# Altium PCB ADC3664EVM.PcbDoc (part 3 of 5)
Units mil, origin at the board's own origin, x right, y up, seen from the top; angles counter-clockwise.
Board outline 3900 x 2716.54 mil, 10 copper layers (Top Layer, L2 GND, L3 PWR, L4 GND, L5 SIG, L6 GND, L7 GND, L8 PWR, L9 GND, Bottom Layer), stack 61.2 mil thick; 332 components, 223 nets, 1425 pads, 969 vias.
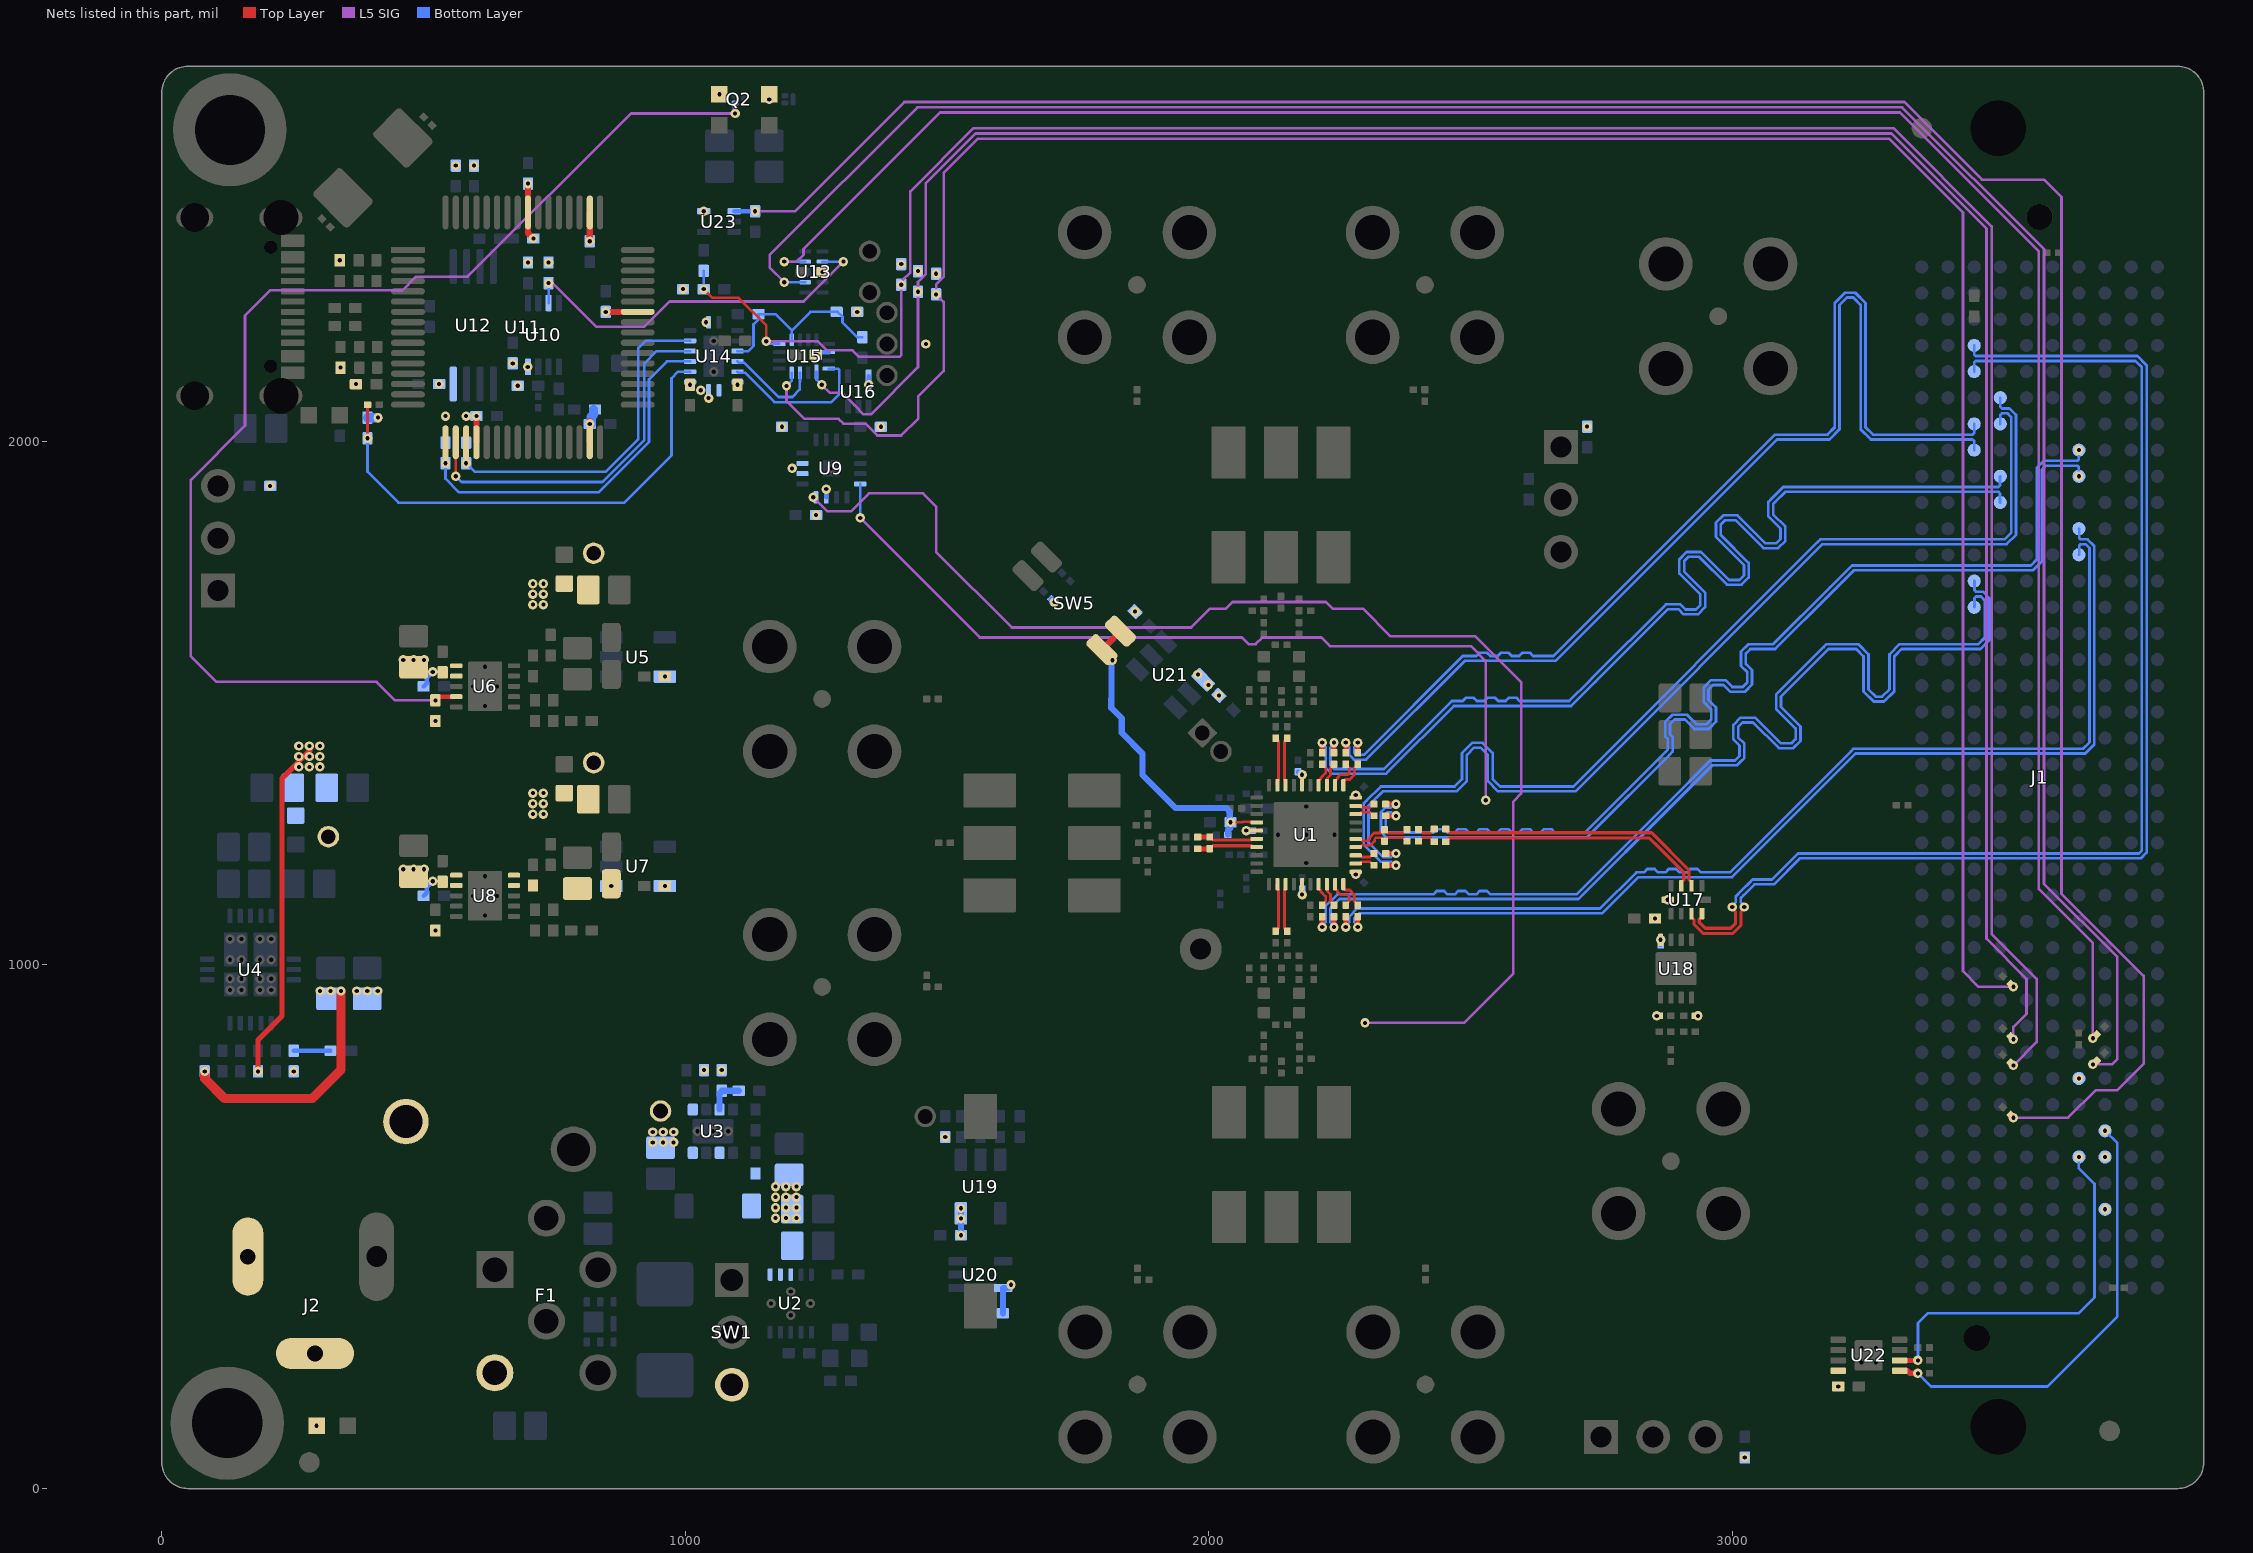
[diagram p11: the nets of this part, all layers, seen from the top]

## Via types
v1: diameter 18, hole 8, Top Layer to Bottom Layer, tented both sides, 952 vias
v2: diameter 40, hole 20, Top Layer to Bottom Layer, tented both sides, 14 vias
v3: diameter 18, hole 8, Top Layer to Bottom Layer, tented bottom, 3 vias

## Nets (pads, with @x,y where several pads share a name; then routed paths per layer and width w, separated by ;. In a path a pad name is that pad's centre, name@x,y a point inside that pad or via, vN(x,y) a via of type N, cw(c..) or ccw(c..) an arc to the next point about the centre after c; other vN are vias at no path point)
1p8V_AVDD: C21.2 C74.2 C75.2 C76.2 FB2.2 PP3.1 U1.5 U1.15 U1.36 U9.8 | length 2600.6
  Top Layer w8: v1(2071.2,1256.67) U1.5@2091.2,1256.67 ; v1(2177.82,1134.31) U1.15@2177.82,1154.31 ; U1.36@2177.82,1343.29 v1(2177.82,1363.29)
  L5 SIG w5: v1(1244.37,1893.18) 1270.87,1866.68 1316.83,1866.68 1350.74,1900.58 1453.75,1900.58 1479.06,1875.27 1479.06,1789.12 1623.6,1644.58 1965.79,1644.58 2001.71,1680.5 2032.12,1680.5 2044.95,1693.33 2223.48,1693.33 2236.31,1680.5 2294.03,1680.5 2346.78,1627.75 2508.63,1627.75 2596.37,1540 2596.37,1327.15 2581.25,1312.02 2581.25,983.33 2487.32,889.4 v1(2298.05,889.4)
  Bottom Layer w5: v1(1244.37,1893.18) U9.8@1249.37,1893.18
  Bottom Layer w8: v1(2071.2,1256.67) C75.2@2082.49,1256.67 ; C76.2@2170,1368.98 2170,1368.19 2175.93,1362.26 2176.79,1362.26 v1(2177.82,1363.29) ; v1(2177.82,1134.31) C74.2@2177.82,1144.88
  other v1: 708.74,1688.25 728.74,1688.25 708.74,1708.25 728.74,1708.25 708.74,1728.25 728.74,1728.25
1p8V_IOVDD: C27.2 C77.2 C78.2 FB3.2 PP4.1 U1.21 U1.30 U9.4 | length 1659.5
  Top Layer w8: v1(2280.18,1172.93) U1.21@2280.18,1177.93 ; U1.30@2280.18,1319.66 v1(2280.18,1324.66)
  L5 SIG w5: v1(1334.01,1853.77) 1562.37,1625.41 2062.89,1625.41 2075.65,1612.66 2089.32,1612.66 2102.08,1625.41 2214.74,1625.41 2231.24,1608.91 2500.47,1608.91 2528.47,1580.91 v1(2528.47,1314.42)
  Bottom Layer w5: v1(1334.01,1853.77) U9.4@1334.01,1918.77
  other v1: 708.74,1288.25 728.74,1288.25 708.74,1308.25 728.74,1308.25 708.74,1328.25 728.74,1328.25
1p8V_LVLSHIFT: C26.2 C46.2 C82.2 R27.1 R28.2 R56.1 R59.2 R60.2 R61.2 R111.2 R122.2 R124.1 R130.2 R148.1 U7.1 U8.9 U8.10 U14.15 U16.5 U19.5 U20.5 U23.5 | length 148.5
  Bottom Layer w5: v1(1099.53,2108.3) U14.15@1099.53,2113.3
  Bottom Layer w9: v1(1350,2108.49) U16.5@1350,2124.23
  Bottom Layer w12: C82.2@1526.23,483.68 v1(1526.21,535.51) ; R124.1@1606.46,334.78 1606.69,335.01 1606.69,382.82 U20.5@1606.92,383.05 1615.82,383.05 ccw(c1615.82,389.15) 1616.84,383.13 U20.5@1621.84,388.13 ; R130.2@1699.72,1697.94 1704.1,1693.55 1705.33,1693.55 v1(1704.72,1692.94) ; U20.5@1621.84,388.13 ccw(c1615.82,389.15) v1(1621.93,389.15) 1621.93,388.22 U20.5@1621.84,388.13
  other v1: 1526.26,483.65 1526.21,515.51 1496.21,671.34 858.46,1150.75 2722.25,2028.25 1459.37,2185.97 1328.11,2247.34 995.55,2290.74 1478.89,2320.15 1444.21,2325.15 1412.13,2338.64 1034.92,2439.49
2p3V: C14.2 C15.2 C18.2 C19.2 C24.2 C25.2 FB1.2 PP2.1 R12.2 R16.2 R26.2 U6.1 U6.2 U8.1 U8.2 | length 854.7
  Top Layer w8: v1(460.98,1182.66) 474.98,1168.66 C24.2@480.98,1168.66 ; v1(460.98,1582.66) 474.98,1568.66 C18.2@480.98,1568.66 ; v1(480.98,1182.66) C24.2@480.98,1168.66 ; v1(480.98,1582.66) C18.2@480.98,1568.66 ; v1(500.98,1182.66) 486.98,1168.66 C24.2@480.98,1168.66 ; v1(500.98,1582.66) 486.98,1568.66 C18.2@480.98,1568.66
  Top Layer w10: v1(183.89,796.75) 183.89,856.68 229.77,902.57 229.77,1356.43 282.4,1409.06
  Bottom Layer w8: R26.2@499.93,1132.05 500.25,1132.05 506.09,1137.89 506.09,1148.51 v1(517.4,1159.81) ; R16.2@499.93,1532.05 500.25,1532.05 506.09,1537.89 506.09,1548.51 v1(517.4,1559.81)
  other v1: 261.89,1378.18 281.89,1378.18 301.89,1378.18 261.89,1398.18 281.89,1398.18 301.89,1398.18 261.89,1418.18 281.89,1418.18 301.89,1418.18
3p3V_AUX: J1.D32
  other v1: 3661.42,783.27
3p3V_EEPROM: C89.2 U22.8
  other v1: 3201.8,194.99
3p3V_Utility: C7.2 C17.2 C23.2 C29.2 C30.2 C36.2 C37.2 C38.2 C39.2 C40.2 C41.2 C44.2 C45.2 C47.2 C55.2 C56.2 C86.2 FB4.1 FB5.1 PP1.1 R5.2 R7.2 R10.2 R15.2 R24.2 R32.2 R33.2 R34.2 R35.1 R37.2 R38.1 R41.2 R47.2 R48.2 R49.2 R51.2 R52.2 R53.2 R54.2 R69.2 R70.2 R75.2 R131.2 U3.4 U3.5 U5.5 U7.5 U9.7 U9.10 U9.11 U10.8 U11.20 U11.31 U11.42 U11.50 U11.56 U12.8 U13.8@1261.85,2323.6 U14.1 U14.2 U14.8 U14.16 U15.14 U17.10 U18.8 U21.4 | length 429.1
  Top Layer w11: v1(847.98,2247.34) U11.42@908.98,2247.34
  Top Layer w12: U11.20@600.91,1998.32 v1(600.91,2048.32) ; v1(699.33,2492.3) U11.56@699.33,2437.3 699.33,2397.82 v1(709.66,2387.5) ; U11.31@817.44,1998.32 v1@817.44,2038.32 ; v1(817.44,2382.3) U11.50@817.44,2437.3
  Bottom Layer w5: v1(1008.98,2108.3) U14.2@1008.98,2113.3 ; v1(1039.41,2227.47) U14.8@1044.41,2227.47
  Bottom Layer w8: v1(1249.02,2165.39) 1251.72,2165.39 1256.72,2170.39 U15.14@1274.02,2170.39 ; C56.2@2862.58,1038.42 v1(2862.58,1047.98)
  Bottom Layer w9: U9.7@1269.05,1893.18 v1(1269.05,1908.92)
  Bottom Layer w18: R52.2@392.95,2045.32 v1(412.95,2045.32) ; v1(817.44,2033.32) 819.41,2033.32 820.25,2034.16 820.25,2047 824.48,2051.23 R38.1@824.48,2060.88
  other v1: 3023.45,59.35 937.5,660.99 957.5,660.99 977.5,660.99 937.5,680.99 957.5,680.99 977.5,680.99 251.89,796.75 1035.7,799.2 1069.29,799.2 2855.22,902.74 2934,902.74 522.48,1065.91 2851.78,1088.72 2876.36,1124.55 960.83,1150.75 522.48,1465.91 2018.88,1514.78 1998.88,1534.78 960.83,1550.75 1978.88,1554.78 1858.78,1674.87 1249.63,1859.23 206.85,1915 1203.78,1948.29 1184.41,2027.82 1373.38,2027.82 541.85,2048.32 581.22,2048.32 1044.41,2082.55 1029.41,2097.55 679.65,2106.22 370.63,2109.54 529.61,2109.54 341.37,2140.87 699.03,2142.22 670.29,2148.91 1261.85,2323.6 699.33,2341.64 738.7,2341.64 340,2345.76 561.54,2526.67 596.22,2526.67
3p3VU_PG: R5.1 R9.2 U3.7 | length 70.4
  Bottom Layer w12: U3.7@1065.29,723.83 1065.29,753.86 1069.29,757.86 R5.1@1069.29,759.83 R9.2@1102.03,759.83
12V: C2.2 C3.2 C6.2 C9.2 C10.2 D1.1 D3.1 D4.1 D5.1 R6.2 R11.2 U2.6 U2.7 U2.8 U3.2 U4.18 | length 462.9
  Top Layer w18: v1(81.89,796.75) 81.89,783.11 120,745 287.48,745 342.26,799.78 v1(342.26,950.2)
  other v1: 295.33,119.85 1172.07,516.64 1192.07,516.64 1212.07,516.64 1172.07,536.64 1192.07,536.64 1212.07,536.64 1172.07,556.64 1192.07,556.64 1212.07,556.64 1172.07,576.64 1192.07,576.64 1212.07,576.64 302.26,950.2 322.26,950.2 372.26,950.2 392.26,950.2 412.26,950.2 1160,2653.11 1065,2663.11
12V_FMC: J1.C35 J1.C37 SW1.3
  other v1: 3711.42,533.27 3711.42,633.27
AIN_N: R87.2 U1.13 | length 93.3
  Top Layer w6.1: U1.13@2146.32,1154.31 2146.32,1146.44 2144,1144.11 2144,1070.85 2149.75,1065.1 R87.2@2149.75,1064.31
AIN_P: R79.2 U1.12 | length 93.3
  Top Layer w6.1: R79.2@2127.15,1064.31 2127.15,1065.1 2132.9,1070.85 2132.9,1144.11 2130.57,1146.44 U1.12@2130.57,1154.31
AVDD_PG: Q2.1@1095,2646.22 R15.1 U6.4 | length 2355.2
  Top Layer w8: v1(522.48,1505.28) 522.48,1506.52 528.32,1512.36 U6.4@562.48,1512.36
  L5 SIG w5: v1(522.48,1505.28) 445.42,1505.28 410,1540.7 104.24,1540.7 55.51,1589.43 55.51,1926.56 158.81,2029.87 158.81,2240.25 206.85,2288.29 459.46,2288.29 485.67,2314.49 584.28,2314.49 896.01,2626.22 v1(1095,2626.22)
  Bottom Layer w9.7: v1(1095,2626.22) Q2.1@1095,2646.22
BIN_N: R91.2 U1.38 | length 93.3
  Top Layer w6.1: U1.38@2146.32,1343.29 2146.32,1351.16 2144,1353.48 2144,1400.97 2144,1426.75 2149.75,1432.5 R91.2@2149.75,1433.29
BIN_P: R99.2 U1.39 | length 93.3
  Top Layer w6.1: R99.2@2127.15,1433.29 2127.15,1432.5 2132.9,1426.75 2132.9,1405.57 2132.9,1353.48 2130.57,1351.16 U1.39@2130.57,1343.29
CLK_N: C54.2 R65.1 U1.7 | length 115.8
  Top Layer w6.1: R65.1@2001.99,1221.75 2007.74,1227.5 2081,1227.5 2083.33,1225.18 U1.7@2091.2,1225.18
  Top Layer w9.7: C54.2@1978.2,1221.75 1994.35,1221.75 1994.9,1222.3 R65.1@2001.2,1222.3
CLK_P: C48.2 R65.2 U1.6 | length 116.3
  Top Layer w6.1: R65.2@2001.2,1244.35 2001.99,1244.35 2007.74,1238.6 2081,1238.6 2083.33,1240.92 U1.6@2091.2,1240.92
  Top Layer w9.7: C48.2@1978.2,1244.35 R65.2@2001.2,1244.35
CTRL: C87.2 C88.2 SW5.3 SW5.4 U1.4 | length 615.6
  Top Layer w5: v1(2041.2,1272.42) 2063.62,1272.42 2064.37,1273.17 2078.04,1273.17 2078.79,1272.42 U1.4@2091.2,1272.42
  Top Layer w12: v1(1815.55,1582.1) SW5.4@1795.55,1602.1 1806.13,1612.68 SW5.3@1830.91,1637.45
  Bottom Layer w12: v1(1815.55,1582.1) 1814.41,1580.95 1814.41,1576.71 1813.79,1576.09 1813.79,1507.94 1813.35,1507.51 1813.35,1490.94 1833.45,1470.85 1833.45,1443.35 1872.93,1403.87 1872.93,1363.32 1936.59,1299.66 2022.44,1299.66 2022.68,1299.91 2032.67,1299.91 2039.7,1292.88 2039.7,1273.92 v1(2041.2,1272.42) 2041.2,1262.58 2036.2,1257.58 C88.2@2036.2,1249.42
DA0_DUT_N: R113.1 U1.19 | length 62
  Top Layer w5.2: U1.19@2240.81,1154.31 2240.81,1146.44 2245.02,1142.22 2245.02,1140.5 2251.47,1134.05 2265.01,1134.05 2268.06,1131.01 2268.06,1121.8 2261.36,1115.1 R113.1@2261.36,1114.31
DA0_DUT_P: R112.1 U1.20 | length 56.7
  Top Layer w5.2: U1.20@2256.56,1154.31 2256.56,1146.44 2259.74,1143.25 2268.82,1143.25 2277.26,1134.82 2277.26,1121.8 2283.96,1115.1 R112.1@2283.96,1114.31
DA0_N: J1.D12 R113.2 | length 2023.1
  Top Layer w9.7: v1(2261.36,1072.26) R113.2@2261.36,1092.26
  Bottom Layer w5.2: v1(2261.36,1072.26) 2261.36,1075.01 2268.06,1081.71 2268.06,1092.87 2283,1107.81 2747.01,1107.81 2816.13,1176.93 2830.77,1176.93 2837.11,1183.27 2851.25,1183.27 2857.58,1176.93 2871.72,1176.93 2878.05,1183.27 2892.19,1183.27 2898.53,1176.93 2912.66,1176.93 2919,1183.27 2933.14,1183.27 2939.47,1176.93 2995.19,1176.93 3225.93,1407.68 3231.32,1413.07 3669.78,1413.07 3681.62,1424.9 3681.62,1796.19 3674.14,1803.67 3665,1803.67 3661.95,1800.62 3661.95,1783.8 J1.D12@3661.42,1783.27
DA0_P: J1.D11 R112.2 | length 2022.6
  Top Layer w9.7: v1(2283.96,1072.26) R112.2@2283.96,1092.26
  Bottom Layer w5.2: v1(2283.96,1072.26) 2283.96,1075.01 2277.26,1081.71 2277.26,1089.06 2286.81,1098.61 2750.82,1098.61 2819.94,1167.73 2999,1167.73 3235.13,1403.87 3673.6,1403.87 3690.82,1421.09 3690.82,1800 3677.95,1812.87 3665,1812.87 3661.95,1815.91 3661.95,1832.73 J1.D11@3661.42,1833.27
DA1_DUT_N: R115.1 U1.17 | length 48.4
  Top Layer w5.2: U1.17@2209.31,1154.31 2209.31,1146.44 2213.52,1142.22 2213.52,1140.34 2222.86,1131.01 2222.86,1121.8 2216.16,1115.1 R115.1@2216.16,1114.31
DA1_DUT_P: R114.1 U1.18 | length 45.7
  Top Layer w5.2: U1.18@2225.06,1154.31 2226.24,1153.13 2226.24,1140.64 2232.06,1134.82 2232.06,1121.8 2238.76,1115.1 R114.1@2238.76,1114.31
DA1_N: J1.H14 R115.2 | length 2018.6
  Top Layer w9.7: v1(2216.16,1072.26) R115.2@2216.16,1092.26
  Bottom Layer w5.2: v1(2216.16,1072.26) 2216.16,1075.01 2222.86,1081.71 2222.86,1112.52 2245.32,1134.97 2428.65,1134.97 2434.98,1141.31 2449.12,1141.31 2455.45,1134.97 2469.59,1134.97 2475.93,1141.31 2490.06,1141.31 2496.4,1134.97 2510.54,1134.97 2516.87,1141.31 2531.01,1141.31 2537.34,1134.97 2701.71,1134.97 2876.4,1309.67 2957.41,1390.68 2984.93,1390.68 3004.83,1390.68 3013.36,1399.21 3013.36,1419.1 3001.5,1430.96 3001.5,1458.48 3015.42,1472.4 3042.94,1472.4 3092.15,1423.19 3112.04,1423.19 3120.57,1431.72 3120.57,1451.61 3083.22,1488.97 3083.22,1516.49 3089.66,1522.93 3174.01,1607.28 3179.4,1612.67 3200,1612.67 3239.98,1612.67 3259.44,1593.21 3259.44,1526.48 3273.51,1512.41 3285.57,1512.41 3299.64,1526.48 3299.64,1593.21 3319.09,1612.67 3328.2,1612.67 3469.38,1612.67 3481.62,1624.9 3481.62,1696.19 3474.14,1703.67 3465,1703.67 3461.95,1700.62 3461.95,1683.8 J1.H14@3461.42,1683.27
DA1_P: J1.H13 R114.2 | length 2018.1
  Top Layer w9.7: v1(2238.76,1072.26) R114.2@2238.76,1092.26
  Bottom Layer w5.2: v1(2238.76,1072.26) 2238.76,1075.01 2232.06,1081.71 2232.06,1108.71 2249.13,1125.77 2705.52,1125.77 2882.91,1303.17 2961.22,1381.48 2981.12,1381.48 3008.64,1381.48 3016.59,1389.43 3022.56,1395.4 3022.56,1422.91 3010.7,1434.77 3010.7,1454.67 3019.23,1463.2 3039.13,1463.2 3088.34,1413.99 3115.85,1413.99 3129.77,1427.91 3129.77,1455.43 3092.42,1492.78 3092.42,1512.68 3096.16,1516.42 3183.21,1603.47 3200,1603.47 3236.17,1603.47 3250.24,1589.4 3250.24,1522.67 3269.69,1503.21 3289.38,1503.21 3308.84,1522.67 3308.84,1589.4 3322.91,1603.47 3328.2,1603.47 3473.19,1603.47 3490.82,1621.09 3490.82,1700 3477.95,1712.87 3465,1712.87 3461.95,1715.91 3461.95,1732.73 J1.H13@3461.42,1733.27
DB0_DUT_N: R117.1 U1.32 | length 62
  Top Layer w5.2: U1.32@2240.81,1343.29 2240.81,1351.16 2245.02,1355.37 2245.02,1357.09 2251.47,1363.54 2265.01,1363.54 2268.06,1366.59 2268.06,1375.8 2261.36,1382.5 R117.1@2261.36,1383.29
DB0_DUT_P: R116.1 U1.31 | length 56.7
  Top Layer w5.2: U1.31@2256.56,1343.29 2256.56,1351.16 2259.74,1354.34 2268.82,1354.34 2277.26,1362.78 2277.26,1375.8 2283.96,1382.5 R116.1@2283.96,1383.29
DB0_N: J1.H8 R117.2 | length 2018.1
  Top Layer w9.7: R117.2@2261.36,1404.62 R117.2@2261.36,1405.33 v1(2261.36,1424.62)
  Bottom Layer w5.2: v1(2261.36,1424.62) 2261.36,1421.88 2268.06,1415.18 2268.06,1401.18 2277.17,1392.06 2299.76,1392.06 2488.5,1580.8 2661.92,1580.8 3084.79,2003.67 3175.86,2003.67 3184.97,2003.67 3204.43,2023.13 3204.43,2260.64 3218.5,2274.71 3230.56,2274.71 3244.63,2260.64 3244.63,2023.13 3264.09,2003.67 3299.64,2003.67 3458.37,2003.67 3461.42,2000.62 J1.H8@3461.42,1983.27
DB0_P: J1.H7 R116.2 | length 2018.6
  Top Layer w9.7: R116.2@2283.96,1404.62 R116.2@2283.96,1405.33 v1(2283.96,1424.62)
  Bottom Layer w5.2: v1(2283.96,1424.62) 2283.96,1421.88 2277.26,1415.18 2277.26,1404.99 2280.98,1401.26 2295.95,1401.26 2484.69,1590 2510.54,1590 2516.87,1596.34 2531.01,1596.34 2537.34,1590 2551.48,1590 2557.82,1596.34 2571.95,1596.34 2578.29,1590 2592.43,1590 2598.76,1596.34 2612.9,1596.34 2619.23,1590 2658.11,1590 3080.98,2012.87 3175.86,2012.87 3181.16,2012.87 3195.23,2026.94 3195.23,2264.45 3214.69,2283.91 3234.37,2283.91 3253.83,2264.45 3253.83,2026.94 3267.9,2012.87 3299.64,2012.87 3458.37,2012.87 3461.42,2015.91 J1.H7@3461.42,2033.27
DB1_DUT_N: R119.1 U1.34 | length 48.4
  Top Layer w5.2: U1.34@2209.31,1343.29 2209.31,1351.16 2213.52,1355.37 2213.52,1357.25 2222.86,1366.59 2222.86,1375.8 2216.16,1382.5 R119.1@2216.16,1383.29
DB1_DUT_P: R118.1 U1.33 | length 45.7
  Top Layer w5.2: U1.33@2225.06,1343.29 2226.24,1344.47 2226.24,1356.96 2232.06,1362.78 2232.06,1375.8 2238.76,1382.5 R118.1@2238.76,1383.29
DB1_N: J1.G10 R119.2 | length 2018.3
  Top Layer w9.7: R119.2@2216.16,1404.62 R119.2@2216.16,1405.33 v1(2216.16,1424.62)
  Bottom Layer w5.2: v1(2216.16,1424.62) 2216.16,1421.88 2222.86,1415.18 2222.86,1377.52 2235.43,1364.95 2337.84,1364.95 2343.23,1370.34 2467.66,1494.78 2691.71,1494.78 2730.3,1533.37 2738.09,1541.16 2876.48,1679.55 2896.38,1679.55 2906.27,1669.65 2933.79,1669.65 2947.71,1683.57 2947.71,1711.09 2907.6,1751.19 2907.6,1771.09 2916.13,1779.62 2936.03,1779.62 2989.4,1726.25 3016.92,1726.25 3030.84,1740.16 3030.84,1767.68 2977.47,1821.05 2977.47,1840.95 2985.99,1849.48 3005.89,1849.48 3059.26,1796.11 3086.78,1796.11 3100.7,1810.03 3100.7,1837.54 3077.54,1860.71 3077.54,1880.61 3081.28,1884.35 3100.6,1903.67 3507.84,1903.67 3510.88,1900.62 3510.88,1883.8 J1.G10@3511.42,1883.27
DB1_P: J1.G9 R118.2 | length 2018.8
  Top Layer w9.7: R118.2@2238.76,1404.62 R118.2@2238.76,1405.33 v1(2238.76,1424.62)
  Bottom Layer w5.2: v1(2238.76,1424.62) 2238.76,1421.88 2232.06,1415.18 2232.06,1381.33 2239.24,1374.15 2334.03,1374.15 2463.85,1503.98 2484.69,1503.98 2491.02,1510.31 2505.16,1510.31 2511.49,1503.98 2525.63,1503.98 2531.97,1510.31 2546.1,1510.31 2552.44,1503.98 2566.58,1503.98 2572.91,1510.31 2587.05,1510.31 2593.38,1503.98 2687.89,1503.98 2726.49,1542.57 2731.58,1547.66 2872.67,1688.75 2900.19,1688.75 2910.08,1678.85 2929.98,1678.85 2938.51,1687.38 2938.51,1707.28 2898.4,1747.38 2898.4,1774.9 2912.32,1788.82 2939.84,1788.82 2993.21,1735.45 3013.11,1735.45 3021.64,1743.97 3021.64,1763.87 2968.27,1817.24 2968.27,1844.76 2982.18,1858.68 3009.7,1858.68 3063.07,1805.31 3082.97,1805.31 3091.5,1813.84 3091.5,1833.73 3068.34,1856.9 3068.34,1884.42 3074.77,1890.86 3096.79,1912.87 3507.84,1912.87 3510.88,1915.91 3510.88,1932.73 J1.G9@3511.42,1933.27
DC-DC_PG: R10.1 R23.2 U4.19 | length 70.2
  Bottom Layer w8: R10.1@251.89,836.12 R23.2@322.11,836.12
DCLK_DUT_N: R108.1 U1.22 | length 39.1
  Top Layer w5.2: U1.22@2280.18,1193.68 2288.05,1193.68 2291.33,1196.95 2307.69,1196.95 2314.39,1190.25 R108.1@2315.18,1190.25
DCLK_DUT_P: R107.1 U1.23 | length 39.1
  Top Layer w5.2: U1.23@2280.18,1209.43 2288.05,1209.43 2291.33,1206.15 2307.69,1206.15 2314.39,1212.85 R107.1@2315.18,1212.85
DCLK_N: J1.G7 R108.2 | length 2017.9
  Top Layer w9.7: R108.2@2337.23,1190.25 v1(2357.23,1190.25)
  Bottom Layer w5.2: v1(2357.23,1190.25) 2354.48,1190.25 2347.78,1196.95 2328.56,1196.95 2323.17,1202.34 2301.05,1224.46 2295.66,1229.85 2295.66,1308.4 2301.05,1313.79 2328.14,1340.87 2463.85,1340.87 2469.15,1340.87 2483.22,1354.94 2483.22,1404.71 2502.67,1424.17 2522.36,1424.17 2541.82,1404.71 2541.82,1354.94 2555.89,1340.87 2645,1340.87 2695.87,1340.87 3162.48,1807.48 3167.87,1812.87 3519.58,1812.87 3532.02,1825.3 3532.02,2046.87 3525.22,2053.67 3514.46,2053.67 3511.42,2050.62 J1.G7@3511.42,2033.27
DCLK_P: J1.G6 R107.2 | length 2017.9
  Top Layer w9.7: R107.2@2337.23,1212.85 v1(2357.23,1212.85)
  Bottom Layer w5.2: v1(2357.23,1212.85) 2354.48,1212.85 2347.78,1206.15 2332.37,1206.15 2304.86,1233.66 2304.86,1304.59 2331.95,1331.67 2463.85,1331.67 2472.96,1331.67 2492.42,1351.13 2492.42,1400.9 2506.49,1414.97 2518.55,1414.97 2532.62,1400.9 2532.62,1351.13 2552.07,1331.67 2645,1331.67 2699.68,1331.67 3171.68,1803.67 3523.39,1803.67 3541.22,1821.49 3541.22,2050.68 3529.03,2062.87 3514.46,2062.87 3511.42,2065.91 J1.G6@3511.42,2083.27
DCLKIN_DUT_N: R103.2 R105.1 U1.24 | length 115.7
  Top Layer w5: U1.24@2280.18,1225.18 2288.05,1225.18 2291.43,1228.55 2308.18,1228.55 2316.38,1236.75 2316.38,1240.05 2319.31,1242.97 2329.44,1242.97 R103.2@2335.18,1237.24 ; R103.2@2335.18,1236.45 R103.2@2335.18,1237.24 ; R105.1@2378.18,1236.15 2377.39,1236.15 2373.59,1239.95 2373.59,1240.05 2370.66,1242.97 2340.92,1242.97 R103.2@2335.18,1237.24
DCLKIN_DUT_P: R103.1 R104.1 U1.25 | length 115.7
  Top Layer w5: U1.25@2280.18,1240.92 2288.05,1240.92 2291.43,1237.55 2304.45,1237.55 2307.38,1240.48 2307.38,1243.77 2315.58,1251.97 2329.44,1251.97 R103.1@2335.18,1257.71 ; R103.1@2335.18,1258.5 R103.1@2335.18,1257.71 ; R104.1@2378.18,1258.8 2377.39,1258.8 2373.59,1255 2373.59,1254.9 2370.66,1251.97 2340.92,1251.97 R103.1@2335.18,1257.71
DCLKIN_N: R72.2 R104.2 | length 36.6
  Top Layer w5: R104.2@2400.23,1258.8 2401.01,1258.8 2404.81,1255 2404.81,1254.9 2407.74,1251.97 2422.71,1251.97 2425.64,1254.9 2425.64,1255.8 2429.44,1259.6 R72.2@2430.23,1259.6
DCLKIN_P: R71.2 R105.2 | length 36.6
  Top Layer w5: R105.2@2400.23,1236.15 2401.01,1236.15 2404.81,1239.95 2404.81,1240.05 2407.74,1242.97 2422.71,1242.97 2425.64,1240.05 2425.64,1239.15 2429.44,1235.35 R71.2@2430.23,1235.35
DCLKIN_SMA_N: R72.1 U17.7 | length 529.4
  Top Layer w6.1: R72.1@2452.27,1259.6 2453.06,1259.6 2456.31,1256.35 2456.31,1256.1 2459.88,1252.53 2845.43,1252.53 2916.84,1181.11 2916.84,1162.48 2920.42,1158.9 2920.75,1158.9 2921.64,1158.02 U17.7@2921.64,1151.13
DCLKIN_SMA_P: R71.1 U17.8 | length 512.7
  Top Layer w6.1: R71.1@2452.27,1235.35 2453.06,1235.35 2456.31,1238.6 2456.31,1238.85 2459.88,1242.43 2841.25,1242.43 2858.92,1224.75 2906.74,1176.93 2906.74,1162.48 2903.17,1158.9 2902.84,1158.9 2901.95,1158.02 U17.8@2901.95,1151.13
EXTGND: F1.3 J2.2 J2.3 TP2.1
FCLK_DUT_N: R110.1 U1.29 | length 39.1
  Top Layer w5.2: U1.29@2280.18,1303.92 2288.05,1303.92 2291.33,1300.64 2307.69,1300.64 2314.39,1307.34 R110.1@2315.18,1307.34
FCLK_DUT_P: R109.1 U1.28 | length 39.1
  Top Layer w5.2: U1.28@2280.18,1288.17 2288.05,1288.17 2291.33,1291.44 2307.69,1291.44 2314.39,1284.74 R109.1@2315.18,1284.74
FCLK_N: J1.D9 R110.2 | length 2017.4
  Top Layer w9.7: R110.2@2337.23,1307.34 v1(2357.23,1307.34)
  Bottom Layer w5.2: v1(2357.23,1307.34) 2354.48,1307.34 2347.78,1300.64 2336.97,1300.64 2328.53,1292.21 2328.53,1253.77 2338.45,1243.85 2721.86,1243.85 2727.25,1249.24 2879.18,1401.17 2885.62,1407.61 2885.62,1435.13 2880.44,1440.32 2880.44,1460.21 2888.97,1468.74 2908.87,1468.74 2926.93,1450.68 2954.45,1450.68 2968.36,1464.6 2968.36,1492.12 2954.17,1506.31 2954.17,1526.21 2962.69,1534.74 2982.59,1534.74 2995.77,1521.57 3023.29,1521.57 3037.2,1535.48 3037.2,1563 3025.35,1574.86 3025.35,1594.75 3033.87,1603.28 3053.77,1603.28 3081.29,1603.28 3192.28,1714.27 3231.88,1753.87 3349.24,1753.87 3573.6,1753.87 3590.82,1771.09 3590.82,1946.4 3598.08,1953.67 3658.37,1953.67 3661.42,1950.62 v1(3661.42,1933.27)
FCLK_P: J1.D8 R109.2 | length 2018.4
  Top Layer w9.7: R109.2@2337.23,1284.74 v1(2357.23,1284.74)
  Bottom Layer w5.2: v1(2357.23,1284.74) 2354.48,1284.74 2347.78,1291.44 2340.78,1291.44 2337.73,1288.4 2337.73,1257.58 2342.26,1253.05 2428.65,1253.05 2434.98,1259.39 2449.12,1259.39 2455.45,1253.05 2469.59,1253.05 2475.93,1259.39 2490.06,1259.39 2496.4,1253.05 2510.54,1253.05 2516.87,1259.39 2531.01,1259.39 2537.34,1253.05 2551.48,1253.05 2557.82,1259.39 2571.95,1259.39 2578.29,1253.05 2592.43,1253.05 2598.76,1259.39 2612.9,1259.39 2619.23,1253.05 2633.37,1253.05 2639.71,1259.39 2653.84,1259.39 2660.18,1253.05 2718.05,1253.05 2872.68,1407.68 2876.42,1411.42 2876.42,1431.32 2871.24,1436.51 2871.24,1464.02 2885.16,1477.94 2912.68,1477.94 2930.74,1459.88 2950.64,1459.88 2959.16,1468.41 2959.16,1488.31 2944.97,1502.5 2944.97,1530.02 2958.88,1543.94 2986.4,1543.94 2999.58,1530.76 3019.47,1530.76 3028,1539.29 3028,1559.19 3016.15,1571.05 3016.15,1598.57 3030.06,1612.48 3057.58,1612.48 3077.48,1612.48 3185.77,1720.77 3228.07,1763.07 3353.05,1763.07 3569.78,1763.07 3581.62,1774.9 3581.62,1950.21 3594.27,1962.87 3658.37,1962.87 3661.42,1965.91 v1(3661.42,1983.27)
FMC_C\S\_DUT_LVLS: R60.1 R143.1 U15.4 | length 4447.5
  Top Layer w5: R143.1@3531.71,962.97 v3(3536.42,958.27)
  L5 SIG w5: v1(1193.15,2106.02) 1193.15,2077.4 1227.45,2043.1 1292.36,2043.1 1301.74,2033.72 1344.15,2033.72 1366.55,2011.32 1412.13,2011.32 1444.85,2044.05 1444.85,2086.22 1493.1,2134.47 1493.1,2266.58 v1(1478.89,2280.78) 1478.89,2299.65 1493.39,2314.15 1493.39,2512.94 1558.54,2578.09 3298.99,2578.09 3440,2437.08 3440,988.27 3470,958.27 v3(3536.42,958.27)
  Bottom Layer w5: v1(1193.15,2106.02) 1203.15,2116.02 U15.4@1203.15,2131.02
FMC_I2C_SCL: R140.1 U13.4 | length 4395.1
  Top Layer w10: v1(3688.23,860.08) R140.1@3694.85,866.7
  L5 SIG w5: v1(1188.98,2343.28) 1212.63,2343.28 1225.48,2356.13 1225.48,2367.09 1486.47,2628.09 2620,2628.09 ; 2790,2628.09 2620,2628.09 ; v1(3688.23,860.08) 3688.23,1041.77 3584.92,1145.08 3584.92,2362.87 3319.7,2628.09 2620,2628.09
  Bottom Layer w5: v1(1188.98,2343.28) U13.4@1228.98,2343.28
FMC_I2C_SDA: R141.1 U13.2 | length 4601.8
  Top Layer w10: v1(3688.23,810.08) R141.1@3694.85,816.7
  L5 SIG w5: v1(1188.98,2303.91) 1161.11,2331.78 1161.11,2356.13 1443.06,2638.09 2620,2638.09 ; 2790,2638.09 2620,2638.09 ; v1(3688.23,810.08) 3724.99,810.08 3734.92,820 3734.92,1015.08 3594.92,1155.08 3594.92,2367.01 3323.84,2638.09 2620,2638.09
  Bottom Layer w5: v1(1188.98,2303.91) U13.2@1228.98,2303.91
FMC_SCLK_DUT_LVLS: R59.1 R144.1 U15.1 | length 4368.2
  Top Layer w5: R144.1@3531.71,862.97 v3(3536.42,858.27)
  L5 SIG w5: v1(1260.39,2107.99) 1275.83,2092.55 1299.42,2092.55 1322.51,2069.47 1340.35,2051.62 1354.11,2051.62 1444.21,2141.73 1444.21,2145.58 v1(1444.21,2285.78) 1444.21,2304.65 1458.71,2319.15 1458.71,2492.4 1554.39,2588.09 3303.13,2588.09 3484.92,2406.3 3484.92,1050.11 3561.42,973.61 3561.42,906.6 3536.42,881.6 v3(3536.42,858.27)
  Bottom Layer w5: U15.1@1250.39,2132.99 1250.39,2117.99 v1(1260.39,2107.99)
FMC_SDI_DUT: R147.2 R151.1 U23.1 | length 4715
  Top Layer w5: R151.1@3531.71,712.97 v1(3536.42,708.27)
  L5 SIG w5: v1(1133.18,2439.49) 1209.54,2439.49 1418.14,2648.09 3327.99,2648.09 3476.07,2500 3595.03,2500 3628.21,2466.83 3628.21,1135.94 3785,979.14 3785,811.05 3734.92,760.97 3693.8,760.97 3641.1,708.27 v1(3536.42,708.27)
  Bottom Layer w8: U23.1@1093.18,2439.49 v1(1133.18,2439.49)
FMC_SDO_DUT_LVLS: R61.1 R145.1 R148.2 R149.2 R150.1 U15.8 | length 4687.6
  Top Layer w5: v1(1034.92,2290.74) 1051.42,2274.24 1101.36,2274.24 1154.53,2221.08 v1(1154.53,2191.14) ; R145.1@3531.71,812.97 v3(3536.42,808.27)
  L5 SIG w5: v1(1154.53,2191.14) 1253.15,2191.14 1270.56,2173.73 1319.06,2173.73 1331.33,2161.47 1409.2,2161.47 1412.13,2164.39 v1(1412.13,2299.27) 1414.61,2301.75 1414.61,2307.78 1429.71,2322.88 1429.71,2477.54 1550.25,2598.09 3307.28,2598.09 3494.92,2410.44 3494.92,1059.36 3580.66,973.61 3580.66,852.51 v3(3536.42,808.27)
  Bottom Layer w5: v1(1034.92,2290.74) R149.2@1034.92,2325.74 ; v1(1154.53,2191.14) 1157.23,2191.14 1162.23,2186.14 U15.8@1179.53,2186.14
FPGA_DCLKIN_N: J1.H5 U17.4 | length 2232
  Top Layer w6.1: U17.4@2941.32,1097.98 2941.32,1092.07 2936.53,1087.28 2936.53,1081.66 2948.05,1070.14 2996.41,1070.14 3005.79,1079.52 3005.79,1101.12 2999.29,1107.62 v1(2999.29,1110.64)
  Bottom Layer w5.2: v1(2999.29,1110.64) 2999.29,1113.14 3006.24,1120.09 3006.24,1131.25 3016.83,1141.84 3032.76,1157.77 3038.15,1163.16 3074.92,1163.16 3124.83,1213.07 3776.19,1213.07 3781.62,1218.5 3781.62,2141.63 3769.58,2153.67 3464.46,2153.67 3461.42,2150.62 J1.H5@3461.42,2133.27
FPGA_DCLKIN_P: J1.H4 U17.3 | length 2280.9
  Top Layer w6.1: U17.3@2921.64,1097.98 2921.64,1091.09 2922.52,1090.2 2922.86,1090.2 2926.43,1086.63 2926.43,1077.47 2943.87,1060.04 3000.59,1060.04 3015.89,1075.34 3015.89,1101.12 3022.39,1107.62 v1(3022.39,1110.64)
  Bottom Layer w5.2: v1(3022.39,1110.64) 3022.39,1113.14 3015.44,1120.09 3015.44,1127.44 3020.64,1132.64 3041.96,1153.96 3078.73,1153.96 3128.64,1203.87 3780,1203.87 3790.82,1214.69 3790.82,2145.44 3773.39,2162.87 3464.46,2162.87 3461.42,2165.91 J1.H4@3461.42,2183.27
FTDI_C\S\_DUT_LVLS: U14.13 U15.3 | length 185.1
  Bottom Layer w5: U14.13@1099.53,2152.67 1101.75,2150.45 1112.4,2150.45 1178.02,2084.83 1204.35,2084.83 1218.15,2098.63 1218.15,2112.85 1218.9,2113.6 U15.3@1218.9,2131.02
FTDI_CSB_SHIFT: R53.1 U11.17 U14.4 | length 721.2
  Top Layer w5: v1(541.85,1958.32) U11.17@541.85,1998.32
  Bottom Layer w5: v1(541.85,1958.32) 541.85,1928.79 567.97,1902.67 834.37,1902.67 930.46,1998.75 930.46,2118.54 964.59,2152.67 U14.4@1008.98,2152.67
FTDI_I2C_SCL: R35.2 U10.3 U13.7 | length 727.2
  L5 SIG w5: v1(738.7,2302.27) 741.19,2299.78 748.78,2299.78 829.55,2219.01 921.46,2219.01 969.54,2267.09 1225.86,2267.09 1276.35,2317.59 1276.35,2317.78 v1(1301.85,2343.28)
  Bottom Layer w5: U10.3@738.7,2264.27 v1(738.7,2302.27) ; U13.7@1261.85,2343.28 v1(1301.85,2343.28)
FTDI_SCLK_DUT_LVLS: U14.14 U15.16 | length 292
  Bottom Layer w5: U14.14@1099.53,2132.99 1101.25,2131.27 1113.79,2131.27 1170.23,2074.83 1278.9,2074.83 1293.81,2089.74 1293.81,2136.39 1291.31,2138.89 U15.16@1274.02,2138.89
FTDI_SCLK_SHIFT: R36.2 R52.1 U14.3 | length 958.4
  Top Layer w5: v1(392.95,2005.95) R36.2@392.95,2070.17
  Bottom Layer w5: v1(392.95,2005.95) 392.95,1942.05 452.01,1882.99 883.27,1882.99 973.36,1973.08 973.36,2120.3 986.05,2132.99 U14.3@1008.98,2132.99
FTDI_SDI_SHIFT: R54.1 U11.19 U14.6 | length 680.4
  Top Layer w5: v1(581.22,1958.32) U11.19@581.22,1998.32
  Bottom Layer w5: v1(581.22,1958.32) 597.72,1941.82 847.76,1941.82 910,2004.06 910,2178.45 923.59,2192.04 U14.6@1008.98,2192.04
FTDI_SDIO_DUT_LVLS: R56.2 R57.2 R58.1 U14.12 U15.9 | length 369.5
  Bottom Layer w5: U14.12@1099.53,2172.36 1120.1,2172.36 1130.05,2182.31 1130.05,2223.58 1139.66,2233.18 R58.1@1139.66,2243.02 1171.83,2243.02 1203.15,2211.7 ; U15.9@1203.15,2194.01 1203.15,2211.7 ; R57.2@1337.95,2199.01 1328.11,2199.01 1299.97,2227.15 1299.97,2238.07 1290.71,2247.34 R56.2@1288.74,2247.34 1238.79,2247.34 1203.15,2211.7
FTDI_SDO_SHIFT: U11.18 U14.5 | length 701.3
  Top Layer w5: v1@561.54,1938.32 U11.18@561.54,1998.32
  Bottom Layer w5: v1(561.54,1933.32) 572.5,1922.36 841.33,1922.36 921.46,2002.48 921.46,2148.91 944.9,2172.36 U14.5@1008.98,2172.36
GA0_FMC: J1.C34 R134.2 U22.1 | length 848.2
  Top Layer w10: U22.1@3319.06,224.99 3333.82,224.99 3338.82,219.99 v1(3354.06,219.99)
  Bottom Layer w5: v1(3354.06,219.99) 3379.05,195 3601.42,195 3735,328.58 3735,659.69 v1(3711.42,683.27)
GA1_FMC: J1.D35 R135.2 U22.2 | length 744.5
  Top Layer w10: U22.2@3319.06,244.68 v1(3354.06,244.68)
  Bottom Layer w5: v1(3354.06,244.68) 3354.06,315.9 3373.15,335 3661.42,335 3691.32,364.9 3691.32,581.79 3661.42,611.69 v1(3661.42,633.27)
